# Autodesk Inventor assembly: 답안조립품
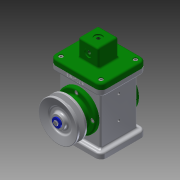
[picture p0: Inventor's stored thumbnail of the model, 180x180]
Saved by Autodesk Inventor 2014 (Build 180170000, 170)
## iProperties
Created: 2017-08
Part Number: 답안조립품
Document SubType Name: Assembly
Designer: 601-03
Author: 601-03
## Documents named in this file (18)
- C:\Users\601-03\Desktop\470808V1007\답안조립품.iam
- C:\Users\601-03\Desktop\470808V1007\본체.ipt
- C:\Users\601-03\Desktop\470808V1007\E-링.ipt
- C:\Users\601-03\Desktop\470808V1007\V-벨트풀리.ipt
- C:\Users\601-03\Desktop\470808V1007\덮개.ipt
- C:\Users\601-03\Desktop\470808V1007\뒤커버.ipt
- C:\Users\601-03\Desktop\470808V1007\링크.ipt
- C:\Users\601-03\Desktop\470808V1007\베어링 17 x 40 x 12.ipt
- C:\Users\601-03\Desktop\470808V1007\볼트 M4 x 8.ipt
- C:\Users\601-03\Desktop\470808V1007\볼트 M4 x 10.ipt
- C:\Users\601-03\Desktop\470808V1007\슬라이더.ipt
- C:\Users\601-03\Desktop\470808V1007\앞커버.ipt
- C:\Users\601-03\Desktop\470808V1007\오일 실 17 30 8.ipt
- C:\Users\601-03\Desktop\470808V1007\와셔 4x16.ipt
- C:\Users\601-03\Desktop\470808V1007\클레비스 핀 6 x 22.ipt
- 클레비스 핀 6 x 22.ipt
- C:\Users\601-03\Desktop\470808V1007\키 4 x 4 x 12.ipt
- C:\Users\601-03\Desktop\470808V1007\편심축.ipt
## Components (2 placed, 2 different names)
1. E-링:1
2. V-벨트풀리:1
